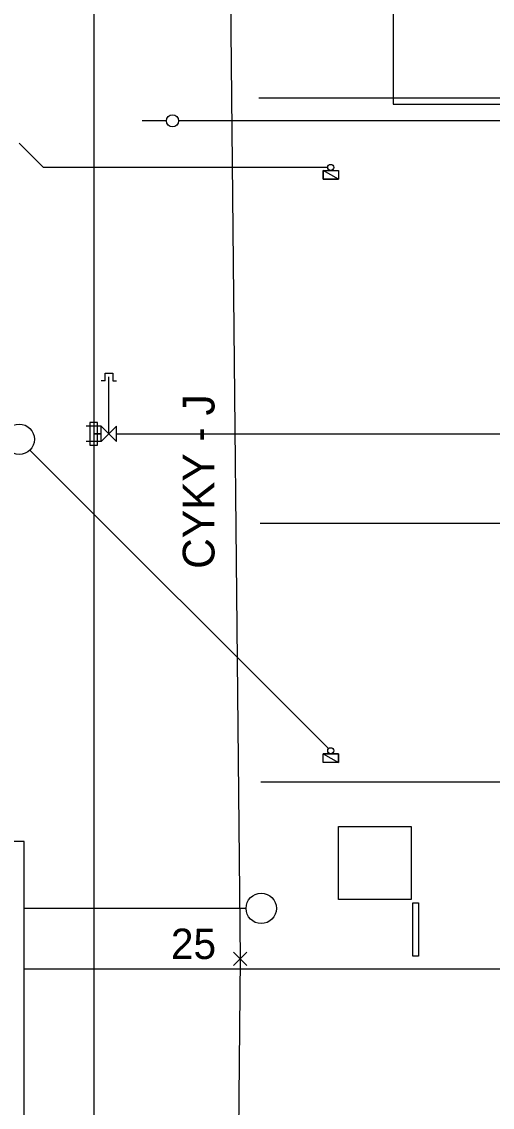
# Model space of a CAD drawing. Extents: x -263993 to -263783, y -1242294 to -1242146.
# Drawn here: x -263926.51 to -263911.03, y -1242243.49 to -1242207.77 of the extents above; entities that cross this region are included whole.
import ezdxf

# ---------------------------------------------------------------- set-up
doc = ezdxf.new("R2010")
doc.units = 0
for name, color, linetype in [('KFA_2D_SITUACIA_DSP', 7, 'Continuous'), ('KFA_ROZVODY_NN_BODY', 7, 'Continuous'), ('KFA_ROZVODY_NN_TRASA', 7, 'Continuous'), ('POPIS', 7, 'Continuous')]:
    doc.layers.add(name, color=color, linetype=linetype)

msp = doc.modelspace()

# ---------------------------------------------------------------- linework, layer by layer
at = {"layer": 'KFA_2D_SITUACIA_DSP'}
for p, q in [((-263914.293, -1242175.482), (-263914.293, -1242210.482)), ((-263924.143, -1242185.14), (-263924.143, -1242250.14)), ((-263908.718, -1242210.282), (-263918.714, -1242210.282)), ((-263914.293, -1242210.482), (-263893.618, -1242210.482)), ((-263921.751, -1242211.032), (-263922.551, -1242211.032)), ((-263903.343, -1242211.032), (-263921.351, -1242211.032)), ((-263925.798, -1242212.562), (-263926.593, -1242211.767)), ((-263916.443, -1242212.562), (-263925.798, -1242212.562)), ((-263916.593, -1242212.952), (-263916.593, -1242212.662)), ((-263916.593, -1242212.662), (-263916.093, -1242212.662)), ((-263916.093, -1242212.952), (-263916.593, -1242212.662)), ((-263916.093, -1242212.952), (-263916.593, -1242212.662)), ((-263916.593, -1242212.662), (-263916.593, -1242212.952)), ((-263916.093, -1242212.662), (-263916.093, -1242212.952)), ((-263916.093, -1242212.952), (-263916.593, -1242212.952)), ((-263916.593, -1242212.952), (-263916.093, -1242212.952)), ((-263923.768, -1242219.582), (-263923.768, -1242219.332)), ((-263923.768, -1242219.332), (-263923.518, -1242219.332)), ((-263923.643, -1242221.332), (-263923.643, -1242219.457)), ((-263923.518, -1242219.332), (-263923.518, -1242219.582)), ((-263923.768, -1242219.582), (-263923.893, -1242219.582)), ((-263923.518, -1242219.582), (-263923.393, -1242219.582)), ((-263923.893, -1242221.082), (-263924.393, -1242221.082)), ((-263924.018, -1242220.957), (-263924.268, -1242220.957)), ((-263924.268, -1242220.957), (-263924.268, -1242221.707)), ((-263924.018, -1242221.707), (-263924.018, -1242220.957)), ((-263923.893, -1242221.582), (-263923.893, -1242221.082)), ((-263923.893, -1242221.082), (-263923.393, -1242221.582)), ((-263923.393, -1242221.082), (-263923.893, -1242221.582)), ((-263923.393, -1242221.582), (-263923.393, -1242221.082)), ((-263923.893, -1242221.582), (-263924.393, -1242221.582)), ((-263924.143, -1242221.332), (-263923.893, -1242221.332)), ((-263923.893, -1242221.332), (-263924.143, -1242221.332)), ((-263923.393, -1242221.332), (-263903.343, -1242221.332)), ((-263916.414, -1242231.691), (-263926.24, -1242221.865)), ((-263924.268, -1242221.707), (-263924.018, -1242221.707)), ((-263908.718, -1242224.282), (-263918.67, -1242224.282)), ((-263916.593, -1242231.862), (-263916.093, -1242231.862)), ((-263916.593, -1242232.152), (-263916.593, -1242231.862)), ((-263916.593, -1242231.862), (-263916.093, -1242232.152)), ((-263916.593, -1242231.862), (-263916.093, -1242232.152)), ((-263916.093, -1242231.862), (-263916.593, -1242231.862)), ((-263916.093, -1242231.862), (-263916.093, -1242232.152)), ((-263916.093, -1242232.152), (-263916.093, -1242231.862)), ((-263916.093, -1242232.152), (-263916.593, -1242232.152)), ((-263905.894, -1242232.793), (-263918.643, -1242232.793)), ((-263916.093, -1242234.257), (-263913.693, -1242234.257)), ((-263916.093, -1242236.657), (-263916.093, -1242234.257)), ((-263913.693, -1242234.257), (-263913.693, -1242236.657)), ((-263926.43, -1242234.749), (-263940.33, -1242234.749)), ((-263926.43, -1242248.649), (-263926.43, -1242234.749)), ((-263919.13, -1242236.949), (-263926.43, -1242236.949)), ((-263913.693, -1242236.657), (-263916.093, -1242236.657)), ((-263907.219, -1242238.949), (-263926.43, -1242238.949))]:
    msp.add_line(p, q, dxfattribs=at)
msp.add_lwpolyline([(-263913.643, -1242238.519), (-263913.643, -1242236.769), (-263913.454, -1242236.769), (-263913.454, -1242238.519), (-263913.643, -1242238.519)], dxfattribs=at)
for centre, radius in [((-263921.551, -1242211.032), 0.2), ((-263916.343, -1242212.562), 0.1), ((-263926.593, -1242221.511), 0.5), ((-263916.343, -1242231.762), 0.1), ((-263918.63, -1242236.949), 0.5)]:
    msp.add_circle(centre, radius, dxfattribs=at)
at = {"layer": 'KFA_ROZVODY_NN_BODY'}
for p, q in [((-263919.541, -1242238.827), (-263919.099, -1242238.385)), ((-263919.099, -1242238.827), (-263919.541, -1242238.385))]:
    msp.add_line(p, q, dxfattribs=at)
at = {"layer": 'KFA_ROZVODY_NN_TRASA'}
for p, q in [((-263919.749, -1242196.637), (-263919.32, -1242238.606)), ((-263919.32, -1242238.606), (-263919.431, -1242248.706))]:
    msp.add_line(p, q, dxfattribs=at)

# ---------------------------------------------------------------- texts
at = {"layer": 'KFA_ROZVODY_NN_BODY'}
msp.add_text('25', height=1, dxfattribs=at).set_placement((-263921.603, -1242238.615))
at = {"layer": 'POPIS'}
msp.add_text('CYKY - J', height=1.045, rotation=90, dxfattribs=at).set_placement((-263920.168, -1242225.775))

doc.saveas('drawing.dxf')
